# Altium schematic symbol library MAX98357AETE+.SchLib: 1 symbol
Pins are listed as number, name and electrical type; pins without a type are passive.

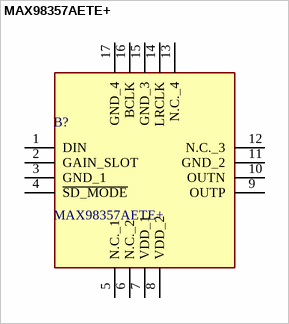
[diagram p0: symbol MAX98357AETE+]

## MAX98357AETE+
designator B?
MAXIM INTEGRATED PRODUCTS - MAX98357AETE+ - AMPLIFIER, CLASS-D, 1-CH, 3.2W, TQFN-16; Manufacturer_Name: Analog Devices; Geometry.Height: 0.8mm
footprint QFN50P300X300X80-17N
pins: 1 DIN, 2 GAIN_SLOT, 3 GND_1, 4 ~{SD_MODE}, 5 N.C._1, 6 N.C._2, 7 VDD_1, 8 VDD_2, 9 OUTP, 10 OUTN, 11 GND_2, 12 N.C._3, 13 N.C._4, 14 LRCLK, 15 GND_3, 16 BCLK, 17 GND_4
